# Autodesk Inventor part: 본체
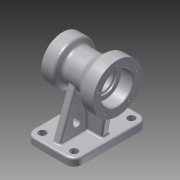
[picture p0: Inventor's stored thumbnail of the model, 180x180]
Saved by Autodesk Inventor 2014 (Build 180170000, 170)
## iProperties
Created: 2015-08
Part Number: 본체
Material: 알루미늄 6061
Document SubType Name: Modeling
Designer: SCD-A09
Density: 2.71 g/cm^3
Appearance: 알루미늄 - 평지
Author: SCD-A09
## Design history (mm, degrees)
sketch "스케치1"
  geometry: L1 (-61, 40)-(61, 40); L2 (61, 40)-(61, -40); L3 (61, -40)-(-61, -40); L4 (-61, -40)-(-61, 40); L5 (-61, 40)-(61, -40); L6 (61, 40)-(-61, -40); 1 further point
  constraints: 12 end point, 2 midpoint, 2 parallel, 1 horizontal, 1 perpendicular
  dimensions: "d0" = 122 distance of L2.end L3.end; "d1" = 80 distance of L1.end L2.end
extrude "돌출1" new body sketch "스케치1" distance "d2" = 12; taper "d3" = 0 deg
fillet "모깎기1" dims "d4" = 14
fillet "모깎기2" dims "d5" = 3
sketch "스케치3"
  geometry: L1 (0, 40)-(9, 40) reference; L2 (90, 63.67)-(90, -74.186); L3 (0, 26)-(0, -26) reference; L4 (90, 40)-(125, 40); L5 (125, 40)-(125, 20); L6 (125, 20)-(116, 14.804); L7 (116, 14.804)-(116, -13.315); L8 (116, -13.315)-(130, -30); L9 (130, -30)-(130, -50); L10 (130, -50)-(90, -50); 1 further point
  constraints: 16 end point, 4 perpendicular, 3 point on line, 2 parallel
  dimensions: "d7" = 90 distance between parallel lines of L3 L2; "d8" = 70 diameter of L5 L2; "d9" = 52 diameter of L7 L2; "d10" = 80 diameter of L9 L2; "d11" = 20 distance of L4.end L5.end; "d12" = 20 distance of L8.end L9.end; "d13" = 60 deg angle of L7 L6; "d14" = 40 deg angle of L7 L8; "d15" = 90 distance between parallel lines of L10 L4
revolve "회전1" sketch "스케치3" stored, may be unused: angle "d16" = 90 deg
sketch "스케치4"
  geometry: L1 (61, 9)-(61, 0) reference; L2 (61, 0)-(-61, 0) reference; L3 (-61, 0)-(-61, 9) reference; L4 (-58, 12)-(58, 12) reference; L5 (51, 12)-(20.667, 95.339); L6 (-51, 12)-(-20.234, 96.53); L7 (20.667, 95.339)-(-20.234, 96.53); L8 (51, 12)-(-51, 12); C1 r 26 at (0, 90) reference; A1 r 3 centre (58, 9) between (61, 9) and (58, 12) reference; A2 r 3 centre (-58, 9) between (-58, 12) and (-61, 9) reference; 1 further point
  constraints: 8 end point, 2 point on line, 1 collinear
  dimensions: "d22" = 70 deg angle of L4 L5; "d23" = 70 deg angle of L4 L6; "d24" = 10 horizontal distance of L5.start L1.start; "d25" = 10 horizontal distance of L3.end L6.start
extrude "돌출2" join sketch "스케치4" stored distance "d26" = 12; taper "d27" = 0 deg
sketch "스케치5"
  geometry: L1 (12, 37)-(12, 6) reference; L2 (12, 6)-(64, 6) reference; L3 (64, 6)-(64, 14.804) reference; L4 (64, 14.804)-(55, 20) reference; L5 (55, 20)-(55, 40) reference; L6 (55, 40)-(125, 40) reference; L7 (125, 40)-(125, 20) reference; L8 (125, 20)-(116, 14.804) reference; L9 (116, 14.804)-(116, -13.315) reference; L10 (116, -13.315)-(130, -30) reference; L11 (130, -30)-(130, -50) reference; L12 (130, -50)-(50, -50) reference; L13 (50, -50)-(50, -30) reference; L14 (50, -30)-(64, -13.315) reference; L15 (64, -13.315)-(64, -6) reference; L16 (64, -6)-(12, -6) reference; L17 (12, -6)-(12, -37) reference; L18 (9, -40)-(0, -40) reference; L19 (0, -40)-(0, 40) reference; L20 (0, 40)-(9, 40) reference; L21 (12, 30)-(82.096, 30); L22 (82.096, 30)-(82.096, -42.36); L23 (82.096, -42.36)-(12, -30); L24 (12, 30)-(12, -30); A1 r 3 centre (9, 37) between (12, 37) and (9, 40) reference; A2 r 3 centre (9, -37) between (9, -40) and (12, -37) reference; 3 further points
  constraints: 8 end point, 5 point on line, 1 collinear, 1 parallel, 1 perpendicular
  dimensions: "d28" = 10 distance from line of L19.end L21; "d29" = 10 vertical distance of L18.start L23.end; "d30" = 80 deg angle of L17 L23
extrude "돌출3" join sketch "스케치5" stored distance "d31" = 12; taper "d32" = 0 deg
sketch "스케치6"
  geometry: C1 r 6 at (-47, -26); C2 r 6 at (-47, 26); C3 r 6 at (47, 26); C4 r 6 at (47, -26); A1 r 11 centre (-47, -26) between (-58, -26) and (-47, -37) reference; A2 r 11 centre (47, -26) between (47, -37) and (58, -26) reference; A3 r 11 centre (47, 26) between (58, 26) and (47, 37) reference; A4 r 11 centre (-47, 26) between (-47, 37) and (-58, 26) reference; 1 further point
  constraints: 4 centre point, 4 coincident
  dimensions: "d34" = 12 diameter of C1; "d35" = 12 diameter of C2; "d36" = 12 diameter of C3; "d37" = 12 diameter of C4
extrude "돌출4" cut sketch "스케치6" stored distance "d38" = 12; taper "d39" = 0 deg
sketch "스케치7"
  geometry: L1 (-6, 12)-(-6, 64.702) reference; L2 (-6, 12)-(-51, 12) reference; L3 (-58, 12)-(-51, 12) reference; L4 (-51, 12)-(-6, 12) reference; L5 (-6, 12)-(-6, 64.702) reference; L6 (-51, 12)-(-25.091, 83.185) reference; L7 (-61, 0)-(-61, 9) reference; L8 (61, 0)-(-61, 0) reference; L9 (61, 9)-(61, 0) reference; L10 (51, 12)-(58, 12) reference; L11 (6, 12)-(51, 12) reference; L12 (6, 64.702)-(6, 12) reference; L13 (25.091, 83.185)-(51, 12) reference; L14 (-22.5, 30)-(-22.5, 36); L15 (-28.5, 30)-(-28.5, 36); L16 (-16.5, 36)-(-16.5, 30); L17 (25.5, 30)-(25.5, 36); L18 (19.5, 30)-(19.5, 36); L19 (31.5, 36)-(31.5, 30); A1 r 26 centre (0, 90) between (-25.091, 83.185) and (-6, 64.702) reference; A2 r 26 centre (0, 90) between (-25.091, 83.185) and (-6, 64.702) reference; A3 r 3 centre (-58, 9) between (-58, 12) and (-61, 9) reference; A4 r 3 centre (58, 9) between (61, 9) and (58, 12) reference; A5 r 26 centre (0, 90) between (6, 64.702) and (25.091, 83.185) reference; A6 r 26 centre (0, 90) between (25.091, 83.185) and (-25.091, 83.185) reference; A7 r 6 centre (-22.5, 30) between (-28.5, 30) and (-16.5, 30); A8 r 6 centre (-22.5, 36) between (-16.5, 36) and (-28.5, 36); A9 r 6 centre (25.5, 30) between (19.5, 30) and (31.5, 30); A10 r 6 centre (25.5, 36) between (31.5, 36) and (19.5, 36); 3 further points
  constraints: 16 end point, 8 point on circle, 8 tangent, 5 parallel, 4 centre point, 2 midpoint, 1 equal radius, 1 horizontal alignment
  dimensions: "d41" = 12 distance between parallel lines of L16 L15; "d42" = 18 dimension on A7 A8; "d43" = 18 distance from line of L2 L14.start; "d44" = 48 distance of point (25.5, 33) point (-22.5, 33); "d45" = 22.5 horizontal distance of A1.centre point (-22.5, 33)
extrude "돌출5" cut sketch "스케치7" stored distance "d46" = 12; taper "d47" = 0 deg
fillet "모깎기3" dims "d48" = 5
fillet "모깎기4" dims "d49" = 3
fillet "모깎기5" dims "d50" = 3
sketch "스케치8"
  geometry: C1 r 40 at (0, 0) reference; C2 r 26 at (0, 0); 1 further point
  constraints: 1 centre point, 1 coincident
  dimensions: "d51" = 52 diameter of C2
extrude "돌출6" cut sketch "스케치8" distance "d52" = 20; taper "d53" = 0 deg
sketch "스케치9"
  geometry: C1 r 26 at (0, 0) reference; C2 r 19 at (0, 0); 1 further point
  constraints: 1 centre point, 1 coincident
  dimensions: "d54" = 38 diameter of C2
extrude "돌출7" cut sketch "스케치9" distance "d55" = 3; taper "d56" = 0 deg
sketch "스케치10"
  geometry: C1 r 35 at (0, 0) reference; C2 r 20 at (0, 0); 1 further point
  constraints: 1 centre point, 1 coincident
  dimensions: "d57" = 40 diameter of C2
extrude "돌출8" cut sketch "스케치10" distance "d58" = 17; taper "d59" = 0 deg
sketch "스케치11"
  geometry: C1 r 20 at (0, 0) reference; C2 r 16 at (0, 0); 1 further point
  constraints: 1 centre point, 1 coincident
  dimensions: "d60" = 32 diameter of C2
extrude "돌출9" cut sketch "스케치11" stored distance "d61" = 40; taper "d62" = 0 deg
sketch "스케치12" dims "d63" = 66
  geometry: C1 r 40 at (0, 0) reference; 7 further points
  constraints: 1 coincident, 1 vertical alignment, 8 other
  dimensions: "d66" = 360 deg dimension on point (0, 0) point (0, 33) (derived)
hole "구멍1" sketch "스케치12" at (0, 33), (-31.385, 10.198), (-19.397, -26.698), (19.397, -26.698), (31.385, 10.198) diameter "d68" = 3.459; stored, may be unused: countersink angle "d72" = 90 deg, drill point angle "d74" = 118 deg; dims "d69" = 10, "d70" = 4, "d71" = 2, "d73" = 13
sketch "스케치13" dims "d75" = 54
  geometry: C1 r 35 at (0, 0) reference; 7 further points
  constraints: 1 coincident, 1 vertical alignment, 8 other
  dimensions: "d78" = 360 deg dimension on point (0, 0) point (0, 27) (derived)
hole "구멍2" sketch "스케치13" at (0, 27), (-25.679, 8.343), (-15.87, -21.843), (15.87, -21.843), (25.679, 8.343) diameter "d80" = 3.459; stored, may be unused: countersink angle "d84" = 90 deg, drill point angle "d86" = 118 deg; dims "d81" = 10, "d82" = 4, "d83" = 2, "d85" = 13
fillet "모깎기6" dims "d87" = 0.3
fillet "모깎기7" dims "d88" = 3
chamfer "모따기1" distance "d89" = 1; stored, may be unused: second distance "d90" = 2, angle "d91" = 45 deg
node "작업 평면1"
sketch "스케치14"
  geometry: L1 (-37, 12)-(-26, 12) reference; L2 (-30, 52.119)-(-30, 15) reference; 2 further points
  constraints: 1 other
  dimensions: "d93" = 24 distance from line of L1 point (-14, 36); "d94" = 16 distance from line of point (-14, 36) L2
feature "엠보싱1" sketch "스케치14" dims "d0" = 122, "d1" = 80, "d95" = 0.5, "d96" = 0
node "솔리드1"
node "절단 모서리 투영1"
node "절단 모서리 투영2"
node "절단 모서리 투영3"
other parameters: "d92" = 104.75
